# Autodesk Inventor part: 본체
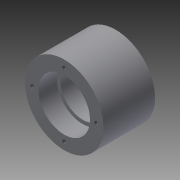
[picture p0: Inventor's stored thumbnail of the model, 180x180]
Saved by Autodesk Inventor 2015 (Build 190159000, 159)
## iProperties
Created: 2019-09
Part Number: 본체
Material: 일반
Document SubType Name: Modeling
Designer: 1010101
Density: 1 g/cm^3
Appearance: 기본값
Author: 1010101
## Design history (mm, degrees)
sketch "스케치1"
  geometry: C1 r 32 at (0, 0); 1 further point
  constraints: 1 centre point, 1 coincident
  dimensions: "d0" = 64 diameter of C1
extrude "돌출1" new body sketch "스케치1" distance "d1" = 42; taper "d2" = 0 deg
sketch "스케치2"
  geometry: C1 r 32 at (0, 0) reference; C2 r 21 at (0, 0)
  constraints: 1 centre point, 1 coincident
  dimensions: "d3" = 42 diameter of C2
extrude "돌출2" cut sketch "스케치2" distance "d4" = 15; taper "d5" = 0 deg
sketch "스케치3"
  geometry: C1 r 21 at (0, 0) reference; C2 r 18 at (0, 0)
  constraints: 1 centre point, 1 coincident
  dimensions: "d6" = 36 diameter of C2
extrude "돌출3" cut sketch "스케치3" stored distance "d7" = 15; taper "d8" = 0 deg
sketch "스케치4"
  geometry: C1 r 18 at (0, 0) reference; C2 r 32 at (0, 0) reference; C3 r 21 at (0, 0)
  constraints: 1 centre point, 1 coincident
  dimensions: "d9" = 42 diameter of C3
extrude "돌출4" cut sketch "스케치4" distance "d10" = 15; taper "d11" = 0 deg
sketch "스케치5" dims "d12" = 52
  geometry: C1 r 21 at (0, 0) reference; C2 r 32 at (0, 0) reference; 2 further points
  constraints: 2 vertical alignment, 1 coincident, 2 other
hole "구멍1" sketch "스케치5" at (0, -26) diameter "d13" = 3.242; stored, may be unused: countersink angle "d17" = 90 deg, drill point angle "d19" = 118 deg; dims "d14" = 8, "d15" = 4, "d16" = 2, "d18" = 10
sketch "스케치6" dims "d23" = 52
  geometry: C1 r 32 at (0, 0) reference; 2 further points
  constraints: 1 coincident, 1 vertical alignment, 2 other
hole "구멍2" sketch "스케치6" at (0, 26) diameter "d24" = 3.242; stored, may be unused: countersink angle "d28" = 90 deg, drill point angle "d30" = 118 deg; dims "d25" = 8, "d26" = 4, "d27" = 2, "d29" = 10
node "솔리드1"
pattern_circular "원형 패턴1" dims angle "d21" = 360 deg
pattern_circular "원형 패턴2" dims angle "d32" = 360 deg
